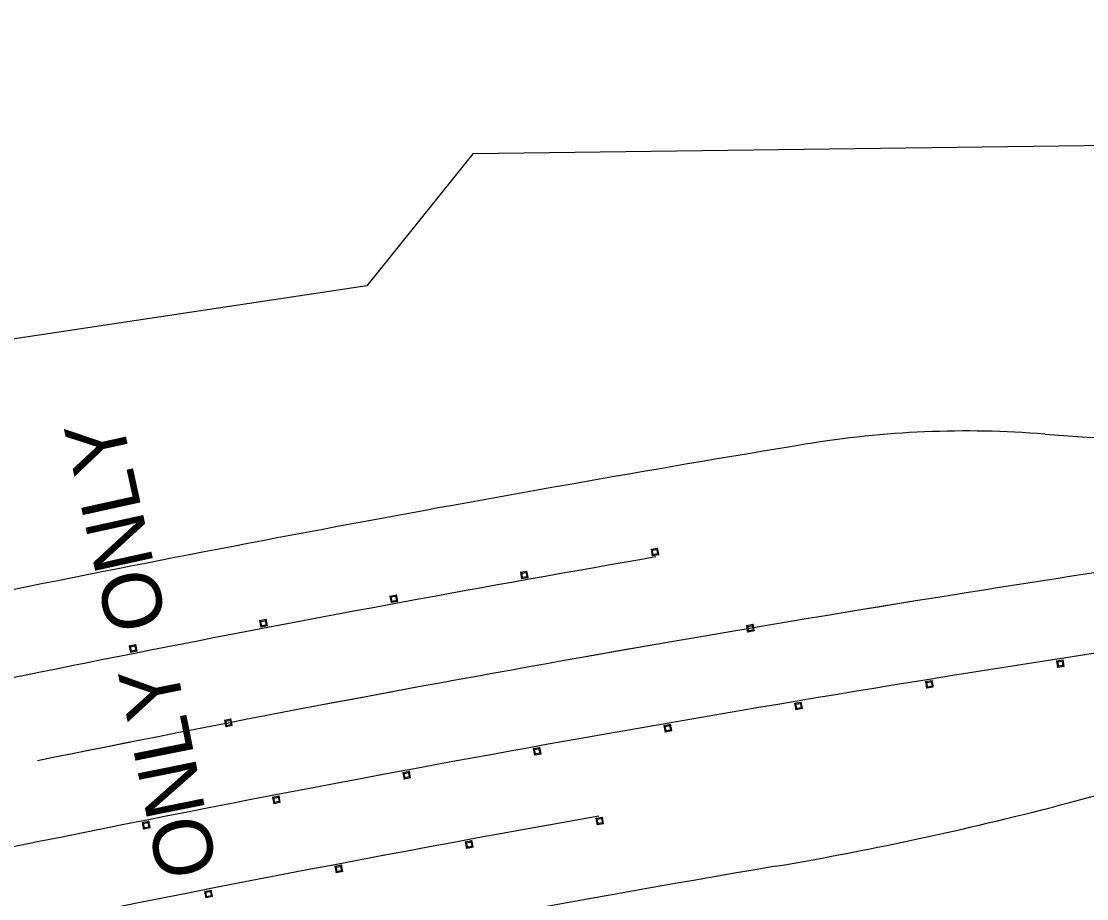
# Model space of a CAD drawing. Extents: x 2471014 to 2497726, y 6959577 to 6980268.
# Drawn here: x 2480487.6 to 2480648.2, y 6967255.3 to 6967387.5 of the extents above; entities that cross this region are included whole.
import ezdxf

# ---------------------------------------------------------------- set-up
doc = ezdxf.new("R2010")
doc.units = 0
for name, color, linetype in [('1', 7, 'Continuous'), ('13', 7, 'Continuous'), ('18', 7, 'Continuous'), ('23', 7, 'Continuous'), ('25', 7, 'Continuous'), ('5', 7, 'Continuous'), ('C-ANNO-NOTE', 7, 'Continuous'), ('p_structure fence', 7, 'Continuous'), ('V7_50', 7, 'Continuous')]:
    doc.layers.add(name, color=color, linetype=linetype)

msp = doc.modelspace()

# ---------------------------------------------------------------- linework, layer by layer
at = {"layer": '1'}
for p, q in [((2480622.18, 6967300.14), (2480612.31, 6967298.53)), ((2480582.73, 6967293.53), (2480572.88, 6967291.8)), ((2480543.36, 6967286.45), (2480533.53, 6967284.61)), ((2480504.08, 6967278.91), (2480494.27, 6967276.95))]:
    msp.add_line(p, q, dxfattribs=at)
at = {"layer": '13'}
msp.add_line((2480645.81, 6967269.85), (2480732.41, 6967292.8), dxfattribs=at)
for centre, radius, start, end in [((2480517.45, 6967754.12), 501, 279.6361, 284.8453), ((2481162.23, 6963956.47), 3351, 99.63605, 101.35083)]:
    msp.add_arc(centre, radius, start, end, dxfattribs=at)
at = {"layer": '18'}
for centre, radius, start, end in [((2480665.63, 6967623.39), 299, 265.4471, 278.5524), ((2480630.07, 6967176.8), 149, 85.4471, 99.3834), ((2481162.23, 6963956.47), 3413, 99.38338, 101.79646)]:
    msp.add_arc(centre, radius, start, end, dxfattribs=at)
at = {"layer": '23'}
for p, q in [((2480582.53, 6967307.97), (2480583.53, 6967308.15)), ((2480582.73, 6967307.83), (2480582.53, 6967307.97)), ((2480582.53, 6967307.97), (2480582.7, 6967306.97)), ((2480582.7, 6967306.97), (2480582.85, 6967307.16)), ((2480583.71, 6967307.15), (2480582.7, 6967306.97)), ((2480582.82, 6967307.3), (2480582.73, 6967307.83)), ((2480582.85, 6967307.16), (2480582.82, 6967307.3)), ((2480583.53, 6967308.15), (2480583.4, 6967307.94)), ((2480583.4, 6967307.94), (2480583.51, 6967307.28)), ((2480583.51, 6967307.28), (2480583.71, 6967307.15)), ((2480583.66, 6967307.41), (2480583.53, 6967308.15)), ((2480583.71, 6967307.15), (2480583.66, 6967307.41)), ((2480562.83, 6967304.51), (2480563.83, 6967304.69)), ((2480563.03, 6967304.36), (2480562.83, 6967304.51)), ((2480562.83, 6967304.51), (2480563.01, 6967303.51)), ((2480563.13, 6967303.83), (2480563.03, 6967304.36)), ((2480563.83, 6967304.69), (2480563.7, 6967304.48)), ((2480563.7, 6967304.48), (2480563.82, 6967303.81)), ((2480563.96, 6967303.95), (2480563.83, 6967304.69)), ((2480564.01, 6967303.69), (2480563.96, 6967303.95)), ((2480563.01, 6967303.51), (2480563.15, 6967303.7)), ((2480564.01, 6967303.69), (2480563.01, 6967303.51)), ((2480563.15, 6967303.7), (2480563.13, 6967303.83)), ((2480563.82, 6967303.81), (2480564.01, 6967303.69)), ((2480543.15, 6967300.92), (2480544.15, 6967301.11)), ((2480543.35, 6967300.78), (2480543.15, 6967300.92)), ((2480543.15, 6967300.92), (2480543.34, 6967299.93)), ((2480543.45, 6967300.25), (2480543.35, 6967300.78)), ((2480544.15, 6967301.11), (2480544.02, 6967300.9)), ((2480544.02, 6967300.9), (2480544.14, 6967300.24)), ((2480544.29, 6967300.38), (2480544.15, 6967301.11)), ((2480544.34, 6967300.11), (2480543.34, 6967299.93)), ((2480543.34, 6967299.93), (2480543.48, 6967300.11)), ((2480543.48, 6967300.11), (2480543.45, 6967300.25)), ((2480544.14, 6967300.24), (2480544.34, 6967300.11)), ((2480544.34, 6967300.11), (2480544.29, 6967300.38)), ((2480523.5, 6967297.23), (2480524.49, 6967297.42)), ((2480523.69, 6967297.08), (2480523.5, 6967297.23)), ((2480523.5, 6967297.23), (2480523.68, 6967296.23)), ((2480524.68, 6967296.42), (2480523.68, 6967296.23)), ((2480523.68, 6967296.23), (2480523.82, 6967296.42)), ((2480523.8, 6967296.56), (2480523.69, 6967297.08)), ((2480523.82, 6967296.42), (2480523.8, 6967296.56)), ((2480524.49, 6967297.42), (2480524.36, 6967297.21)), ((2480524.36, 6967297.21), (2480524.49, 6967296.54)), ((2480524.63, 6967296.68), (2480524.49, 6967297.42)), ((2480524.49, 6967296.54), (2480524.68, 6967296.42)), ((2480524.68, 6967296.42), (2480524.63, 6967296.68)), ((2480596.93, 6967296.49), (2480597.93, 6967296.66)), ((2480597.13, 6967296.34), (2480596.93, 6967296.49)), ((2480596.93, 6967296.49), (2480597.1, 6967295.49)), ((2480597.22, 6967295.81), (2480597.13, 6967296.34)), ((2480597.93, 6967296.66), (2480597.79, 6967296.45)), ((2480597.79, 6967296.45), (2480597.91, 6967295.79)), ((2480598.05, 6967295.92), (2480597.93, 6967296.66)), ((2480598.1, 6967295.66), (2480598.05, 6967295.92)), ((2480597.1, 6967295.49), (2480597.24, 6967295.67)), ((2480598.1, 6967295.66), (2480597.1, 6967295.49)), ((2480597.24, 6967295.67), (2480597.22, 6967295.81)), ((2480597.91, 6967295.79), (2480598.1, 6967295.66)), ((2480503.86, 6967293.41), (2480504.85, 6967293.61)), ((2480504.06, 6967293.27), (2480503.86, 6967293.41)), ((2480503.86, 6967293.41), (2480504.05, 6967292.42)), ((2480504.16, 6967292.74), (2480504.06, 6967293.27)), ((2480504.19, 6967292.61), (2480504.16, 6967292.74)), ((2480504.85, 6967293.61), (2480504.72, 6967293.4)), ((2480504.72, 6967293.4), (2480504.86, 6967292.74)), ((2480505, 6967292.88), (2480504.85, 6967293.61)), ((2480504.86, 6967292.74), (2480505.05, 6967292.61)), ((2480505.05, 6967292.61), (2480505, 6967292.88)), ((2480505.05, 6967292.61), (2480504.05, 6967292.42)), ((2480504.05, 6967292.42), (2480504.19, 6967292.61)), ((2480643.69, 6967291.16), (2480644.69, 6967291.32)), ((2480643.88, 6967291.01), (2480643.69, 6967291.16)), ((2480643.69, 6967291.16), (2480643.84, 6967290.16)), ((2480644.69, 6967291.32), (2480644.55, 6967291.12)), ((2480644.55, 6967291.12), (2480644.65, 6967290.45)), ((2480644.8, 6967290.58), (2480644.69, 6967291.32)), ((2480643.84, 6967290.16), (2480643.98, 6967290.34)), ((2480644.84, 6967290.32), (2480643.84, 6967290.16)), ((2480643.96, 6967290.48), (2480643.88, 6967291.01)), ((2480643.98, 6967290.34), (2480643.96, 6967290.48)), ((2480644.65, 6967290.45), (2480644.84, 6967290.32)), ((2480644.84, 6967290.32), (2480644.8, 6967290.58)), ((2480623.93, 6967288.03), (2480624.93, 6967288.19)), ((2480624.13, 6967287.88), (2480623.93, 6967288.03)), ((2480623.93, 6967288.03), (2480624.09, 6967287.03)), ((2480624.21, 6967287.35), (2480624.13, 6967287.88)), ((2480624.93, 6967288.19), (2480624.79, 6967287.99)), ((2480624.79, 6967287.99), (2480624.9, 6967287.32)), ((2480625.05, 6967287.46), (2480624.93, 6967288.19)), ((2480624.09, 6967287.03), (2480624.23, 6967287.21)), ((2480625.09, 6967287.19), (2480624.09, 6967287.03)), ((2480624.23, 6967287.21), (2480624.21, 6967287.35)), ((2480624.9, 6967287.32), (2480625.09, 6967287.19)), ((2480625.09, 6967287.19), (2480625.05, 6967287.46)), ((2480604.19, 6967284.78), (2480605.19, 6967284.95)), ((2480604.39, 6967284.63), (2480604.19, 6967284.78)), ((2480604.19, 6967284.78), (2480604.36, 6967283.78)), ((2480604.48, 6967284.11), (2480604.39, 6967284.63)), ((2480605.19, 6967284.95), (2480605.06, 6967284.75)), ((2480605.06, 6967284.75), (2480605.17, 6967284.08)), ((2480605.32, 6967284.21), (2480605.19, 6967284.95)), ((2480604.36, 6967283.78), (2480604.5, 6967283.97)), ((2480605.36, 6967283.95), (2480604.36, 6967283.78)), ((2480604.5, 6967283.97), (2480604.48, 6967284.11)), ((2480605.17, 6967284.08), (2480605.36, 6967283.95)), ((2480605.36, 6967283.95), (2480605.32, 6967284.21)), ((2480518.2, 6967282.21), (2480519.2, 6967282.4)), ((2480518.4, 6967282.06), (2480518.2, 6967282.21)), ((2480518.2, 6967282.21), (2480518.4, 6967281.21)), ((2480518.51, 6967281.54), (2480518.4, 6967282.06)), ((2480518.53, 6967281.4), (2480518.51, 6967281.54)), ((2480519.2, 6967282.4), (2480519.07, 6967282.19)), ((2480519.07, 6967282.19), (2480519.2, 6967281.53)), ((2480519.34, 6967281.67), (2480519.2, 6967282.4)), ((2480519.2, 6967281.53), (2480519.39, 6967281.4)), ((2480519.39, 6967281.4), (2480519.34, 6967281.67)), ((2480584.48, 6967281.42), (2480585.47, 6967281.59)), ((2480584.67, 6967281.27), (2480584.48, 6967281.42)), ((2480584.48, 6967281.42), (2480584.65, 6967280.42)), ((2480585.47, 6967281.59), (2480585.34, 6967281.39)), ((2480585.6, 6967280.86), (2480585.47, 6967281.59)), ((2480519.39, 6967281.4), (2480518.4, 6967281.21)), ((2480518.4, 6967281.21), (2480518.53, 6967281.4)), ((2480584.65, 6967280.42), (2480584.79, 6967280.6)), ((2480585.65, 6967280.59), (2480584.65, 6967280.42)), ((2480584.76, 6967280.74), (2480584.67, 6967281.27)), ((2480584.79, 6967280.6), (2480584.76, 6967280.74)), ((2480585.34, 6967281.39), (2480585.46, 6967280.72)), ((2480585.46, 6967280.72), (2480585.65, 6967280.59)), ((2480585.65, 6967280.59), (2480585.6, 6967280.86)), ((2480564.78, 6967277.93), (2480565.78, 6967278.11)), ((2480564.98, 6967277.79), (2480564.78, 6967277.93)), ((2480564.78, 6967277.93), (2480564.96, 6967276.93)), ((2480564.96, 6967276.93), (2480565.1, 6967277.12)), ((2480565.96, 6967277.11), (2480564.96, 6967276.93)), ((2480565.07, 6967277.26), (2480564.98, 6967277.79)), ((2480565.1, 6967277.12), (2480565.07, 6967277.26)), ((2480565.78, 6967278.11), (2480565.64, 6967277.91)), ((2480565.64, 6967277.91), (2480565.76, 6967277.24)), ((2480565.76, 6967277.24), (2480565.96, 6967277.11)), ((2480565.91, 6967277.38), (2480565.78, 6967278.11)), ((2480565.96, 6967277.11), (2480565.91, 6967277.38)), ((2480545.1, 6967274.33), (2480546.1, 6967274.52)), ((2480545.3, 6967274.19), (2480545.1, 6967274.33)), ((2480545.1, 6967274.33), (2480545.29, 6967273.34)), ((2480546.28, 6967273.52), (2480545.29, 6967273.34)), ((2480545.29, 6967273.34), (2480545.42, 6967273.52)), ((2480545.4, 6967273.66), (2480545.3, 6967274.19)), ((2480545.42, 6967273.52), (2480545.4, 6967273.66)), ((2480546.1, 6967274.52), (2480545.97, 6967274.31)), ((2480545.97, 6967274.31), (2480546.09, 6967273.65)), ((2480546.09, 6967273.65), (2480546.28, 6967273.52)), ((2480546.23, 6967273.79), (2480546.1, 6967274.52)), ((2480546.28, 6967273.52), (2480546.23, 6967273.79)), ((2480525.45, 6967270.62), (2480526.44, 6967270.81)), ((2480525.65, 6967270.47), (2480525.45, 6967270.62)), ((2480525.45, 6967270.62), (2480525.64, 6967269.62)), ((2480525.75, 6967269.95), (2480525.65, 6967270.47)), ((2480526.44, 6967270.81), (2480526.31, 6967270.6)), ((2480526.31, 6967270.6), (2480526.44, 6967269.94)), ((2480526.58, 6967270.08), (2480526.44, 6967270.81)), ((2480526.63, 6967269.81), (2480525.64, 6967269.62)), ((2480525.64, 6967269.62), (2480525.77, 6967269.81)), ((2480525.77, 6967269.81), (2480525.75, 6967269.95)), ((2480526.44, 6967269.94), (2480526.63, 6967269.81)), ((2480526.63, 6967269.81), (2480526.58, 6967270.08)), ((2480505.81, 6967266.78), (2480506.81, 6967266.98)), ((2480506.81, 6967266.98), (2480506.68, 6967266.78)), ((2480506.95, 6967266.25), (2480506.81, 6967266.98)), ((2480574.21, 6967267.43), (2480575.21, 6967267.61)), ((2480574.41, 6967267.28), (2480574.21, 6967267.43)), ((2480574.21, 6967267.43), (2480574.39, 6967266.43)), ((2480574.51, 6967266.76), (2480574.41, 6967267.28)), ((2480575.21, 6967267.61), (2480575.08, 6967267.4)), ((2480575.08, 6967267.4), (2480575.2, 6967266.74)), ((2480575.34, 6967266.87), (2480575.21, 6967267.61)), ((2480506.01, 6967266.64), (2480505.81, 6967266.78)), ((2480505.81, 6967266.78), (2480506.01, 6967265.79)), ((2480506.12, 6967266.12), (2480506.01, 6967266.64)), ((2480507.01, 6967265.99), (2480506.01, 6967265.79)), ((2480506.01, 6967265.79), (2480506.15, 6967265.98)), ((2480506.15, 6967265.98), (2480506.12, 6967266.12)), ((2480506.68, 6967266.78), (2480506.81, 6967266.11)), ((2480506.81, 6967266.11), (2480507.01, 6967265.99)), ((2480507.01, 6967265.99), (2480506.95, 6967266.25)), ((2480574.39, 6967266.43), (2480574.53, 6967266.62)), ((2480575.39, 6967266.61), (2480574.39, 6967266.43)), ((2480574.53, 6967266.62), (2480574.51, 6967266.76)), ((2480575.2, 6967266.74), (2480575.39, 6967266.61)), ((2480575.39, 6967266.61), (2480575.34, 6967266.87)), ((2480554.53, 6967263.87), (2480555.53, 6967264.06)), ((2480554.73, 6967263.73), (2480554.53, 6967263.87)), ((2480554.53, 6967263.87), (2480554.71, 6967262.88)), ((2480555.53, 6967264.06), (2480555.39, 6967263.85)), ((2480555.39, 6967263.85), (2480555.52, 6967263.19)), ((2480555.66, 6967263.32), (2480555.53, 6967264.06)), ((2480555.71, 6967263.06), (2480554.71, 6967262.88)), ((2480554.71, 6967262.88), (2480554.85, 6967263.06)), ((2480554.83, 6967263.2), (2480554.73, 6967263.73)), ((2480554.85, 6967263.06), (2480554.83, 6967263.2)), ((2480555.52, 6967263.19), (2480555.71, 6967263.06)), ((2480555.71, 6967263.06), (2480555.66, 6967263.32)), ((2480534.87, 6967260.2), (2480535.86, 6967260.39)), ((2480535.07, 6967260.06), (2480534.87, 6967260.2)), ((2480534.87, 6967260.2), (2480535.06, 6967259.2)), ((2480536.05, 6967259.39), (2480535.06, 6967259.2)), ((2480535.06, 6967259.2), (2480535.19, 6967259.39)), ((2480535.17, 6967259.53), (2480535.07, 6967260.06)), ((2480535.19, 6967259.39), (2480535.17, 6967259.53)), ((2480535.86, 6967260.39), (2480535.73, 6967260.18)), ((2480535.73, 6967260.18), (2480535.86, 6967259.52)), ((2480536, 6967259.66), (2480535.86, 6967260.39)), ((2480535.86, 6967259.52), (2480536.05, 6967259.39)), ((2480536.05, 6967259.39), (2480536, 6967259.66)), ((2480515.23, 6967256.41), (2480516.22, 6967256.6)), ((2480515.43, 6967256.27), (2480515.23, 6967256.41)), ((2480515.23, 6967256.41), (2480515.42, 6967255.41)), ((2480515.53, 6967255.74), (2480515.43, 6967256.27)), ((2480515.56, 6967255.6), (2480515.53, 6967255.74)), ((2480516.22, 6967256.6), (2480516.09, 6967256.4)), ((2480516.09, 6967256.4), (2480516.22, 6967255.73)), ((2480516.37, 6967255.87), (2480516.22, 6967256.6)), ((2480516.22, 6967255.73), (2480516.42, 6967255.61)), ((2480516.42, 6967255.61), (2480516.37, 6967255.87)), ((2480516.42, 6967255.61), (2480515.42, 6967255.41)), ((2480515.42, 6967255.41), (2480515.56, 6967255.6))]:
    msp.add_line(p, q, dxfattribs=at)
for points in [[(2480583.51, 6967307.28), (2480582.85, 6967307.16), (2480582.73, 6967307.83), (2480583.4, 6967307.94)], [(2480563.82, 6967303.81), (2480563.15, 6967303.7), (2480563.03, 6967304.36), (2480563.7, 6967304.48)], [(2480544.14, 6967300.24), (2480543.48, 6967300.11), (2480543.35, 6967300.78), (2480544.02, 6967300.9)], [(2480524.49, 6967296.54), (2480523.82, 6967296.42), (2480523.69, 6967297.08), (2480524.36, 6967297.21)], [(2480597.91, 6967295.79), (2480597.24, 6967295.67), (2480597.13, 6967296.34), (2480597.79, 6967296.45)], [(2480504.86, 6967292.74), (2480504.19, 6967292.61), (2480504.06, 6967293.27), (2480504.72, 6967293.4)], [(2480644.65, 6967290.45), (2480643.98, 6967290.34), (2480643.88, 6967291.01), (2480644.55, 6967291.12)], [(2480624.9, 6967287.32), (2480624.23, 6967287.21), (2480624.13, 6967287.88), (2480624.79, 6967287.99)], [(2480605.17, 6967284.08), (2480604.5, 6967283.97), (2480604.39, 6967284.63), (2480605.06, 6967284.75)], [(2480519.2, 6967281.53), (2480518.53, 6967281.4), (2480518.4, 6967282.06), (2480519.07, 6967282.19)], [(2480585.46, 6967280.72), (2480584.79, 6967280.6), (2480584.67, 6967281.27), (2480585.34, 6967281.39)], [(2480565.76, 6967277.24), (2480565.1, 6967277.12), (2480564.98, 6967277.79), (2480565.64, 6967277.91)], [(2480546.09, 6967273.65), (2480545.42, 6967273.52), (2480545.3, 6967274.19), (2480545.97, 6967274.31)], [(2480526.44, 6967269.94), (2480525.77, 6967269.81), (2480525.65, 6967270.47), (2480526.31, 6967270.6)], [(2480575.2, 6967266.74), (2480574.53, 6967266.62), (2480574.41, 6967267.28), (2480575.08, 6967267.4)], [(2480506.81, 6967266.11), (2480506.15, 6967265.98), (2480506.01, 6967266.64), (2480506.68, 6967266.78)], [(2480555.52, 6967263.19), (2480554.85, 6967263.06), (2480554.73, 6967263.73), (2480555.39, 6967263.85)], [(2480535.86, 6967259.52), (2480535.19, 6967259.39), (2480535.07, 6967260.06), (2480535.73, 6967260.18)], [(2480516.22, 6967255.73), (2480515.56, 6967255.6), (2480515.43, 6967256.27), (2480516.09, 6967256.4)]]:
    msp.add_lwpolyline(points, close=True, dxfattribs=at)
at = {"layer": '25'}
for radius, start, end in [(3400, 99.80468, 102.41527), (3375, 97.47173, 100.65474), (3375, 100.65474, 102.4238), (3363, 100.06198, 102.08195)]:
    msp.add_arc((2481162.23, 6963956.47), radius, start, end, dxfattribs=at)
at = {"layer": '5'}
msp.add_arc((2479474.04, 6969335.88), 8460, 6.37617, 6.37617, dxfattribs=at)
at = {"layer": 'C-ANNO-NOTE'}
msp.add_arc((2481162.23, 6963956.47), 3387, 98.54017, 101.44721, dxfattribs=at)
at = {"layer": 'V7_50'}
msp.add_lwpolyline([(2481147.36, 6967423.75), (2480793.84, 6967370.67), (2480555.68, 6967367.58), (2480539.68, 6967347.67), (2480461.84, 6967335.98), (2480420.21, 6967349.5), (2480410.08, 6967345.94), (2480421.83, 6967319.12), (2480415.63, 6967313.77), (2480429.34, 6967302.76), (2480444.99, 6967295.17), (2480459.46, 6967292.51), (2480472.21, 6967292.15), (2480480.9, 6967234.3), (2480473.12, 6967225.44), (2480468.38, 6967217.08), (2480469.85, 6967216.31), (2480687.16, 6967249.95), (2480686.35, 6967245.6), (2480704.04, 6967105.84), (2480746.63, 6967111.84), (2480904.51, 6967134.66)], dxfattribs=at)

# ---------------------------------------------------------------- texts
at = {"layer": 'p_structure fence'}
for rotation, p in [(102.4402, (2480509.61, 6967296.66)), (101.3753, (2480517.22, 6967259.41))]:
    msp.add_text('ONLY', height=8.898, rotation=rotation, dxfattribs=at).set_placement(p)

doc.saveas('drawing.dxf')
